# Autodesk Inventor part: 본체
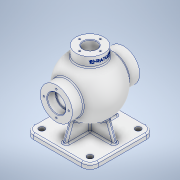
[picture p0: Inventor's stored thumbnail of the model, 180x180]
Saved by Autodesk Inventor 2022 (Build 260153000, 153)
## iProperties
Created: 2024-04
Part Number: 본체
Material: 알루미늄 6061
Document SubType Name: Modeling
Designer: user
Density: 2.7 g/cm^3
Appearance: 알루미늄 - 평지
Mass: 1526.73 g
Surface Area: 1173.98 cm^2
Volume: 565.456 cm^3
Author: user
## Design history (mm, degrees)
sketch "스케치1"
  geometry: L1 (64.8, 0)-(-10.8, 0) reference; L2 (0, -185.251)-(0, 154.667) reference; L3 (31, 65)-(31, 44.215); L4 (31, -44.215)-(31, -65); L5 (31, 65)-(0, 65); L6 (31, -65)-(0, -65); L7 (0, -65)-(0, 65); L8 (0, -136.691)-(0, 106.107); A1 r 54 centre (0, 0) between (31, -44.215) and (31, 44.215); 1 further point
  constraints: 12 end point, 4 point on line, 2 perpendicular, 2 point on circle, 2 vertical, 1 centre point, 1 coincident, 1 collinear, 1 symmetric about line
  dimensions: "d0" = 108 diameter of A1; "d2" = 31 distance between parallel lines of L4 L2; "d4" = 130 distance of L4.end L3.start
revolve "회전1" sketch "스케치1" stored, may be unused: angle "d5" = 360 deg
sketch "스케치2"
  geometry: C1 r 27 at (0, 0); 1 further point
  constraints: 1 centre point, 1 coincident
  dimensions: "d6" = 54 diameter of C1
extrude "돌출1" join sketch "스케치2" distance "d7" = 65; taper "d8" = 0 deg
node "작업 평면1"
sketch "스케치3"
  geometry: L1 (62.5, 62.5)-(-62.5, 62.5); L2 (-62.5, 62.5)-(-62.5, -62.5); L3 (-62.5, -62.5)-(62.5, -62.5); L4 (62.5, -62.5)-(62.5, 62.5); L5 (62.5, 62.5)-(-62.5, -62.5); L6 (-62.5, 62.5)-(62.5, -62.5); 1 further point
  constraints: 12 end point, 2 midpoint, 2 parallel, 1 horizontal, 1 perpendicular
  dimensions: "d10" = 125 distance of L3.end L1.start; "d11" = 125 distance of L2.end L3.end
extrude "돌출2" join sketch "스케치3" distance "d12" = 10; taper "d13" = 0 deg
sketch "스케치4"
  geometry: L1 (0, 23.202)-(0, -23.202); L2 (0, -23.202)-(-75, -50.5); L3 (-75, -62.5)-(-75, 62.5) reference; L4 (0, 23.202)-(-75, 50.5); L5 (-75, 50.5)-(-75, -50.5); L6 (-102, 0)-(17, 0) reference; L7 (0, -87.5)-(0, 87.5) reference; L8 (-85, -62.5)-(-75, -62.5) reference; 2 further points
  constraints: 8 end point, 2 symmetric about line, 1 collinear, 1 parallel, 1 point on line, 1 vertical
  dimensions: "d14" = 20 deg angle of L8 L2; "d15" = 12 distance of L3.start L2.end
extrude "돌출3" join sketch "스케치4" stored distance "d16" = 8; taper "d17" = 0 deg
sketch "스케치5"
  geometry: L1 (-23.202, 0)-(23.202, 0); L2 (23.202, 0)-(50.5, -75); L3 (62.5, -75)-(-62.5, -75) reference; L4 (-23.202, 0)-(-50.5, -75); L5 (-50.5, -75)-(50.5, -75); L6 (0, -102)-(0, 17) reference; L7 (62.5, -85)-(62.5, -75) reference; L8 (-62.5, -85)-(-62.5, -75) reference; L9 (-87.5, 0)-(87.5, 0) reference; 1 further point
  constraints: 8 end point, 2 point on line, 2 symmetric about line, 1 collinear, 1 horizontal, 1 parallel
  dimensions: "d20" = 20 deg angle of L8 L4; "d21" = 12 distance of L3.end L4.end
extrude "돌출4" join sketch "스케치5" stored distance "d22" = 8; taper "d23" = 0 deg
sketch "스케치6"
  geometry: L1 (-31, -65)-(31, -65) reference; L2 (0, -65)-(17.5, -65); L3 (17.5, -65)-(17.5, -49); L4 (17.5, -49)-(0, -49); L5 (0, -49)-(0, -65); L6 (0, -49)-(15, -49); L7 (15, -49)-(15, -41.364); L8 (15, -41.364)-(0, -41.364); L9 (0, -41.364)-(0, -49); L10 (0, -91)-(0, 91) reference; L11 (75.6, 0)-(-75.6, 0) reference; L12 (-31, 65)-(31, 65) reference; L13 (0, 65)-(17.5, 65); L14 (17.5, 65)-(17.5, 49); L15 (17.5, 49)-(0, 49); L16 (0, 49)-(0, 65); L17 (0, 49)-(15, 49); L18 (15, 49)-(15, 41.364); L19 (15, 41.364)-(0, 41.364); L20 (0, 41.364)-(0, 49); L21 (0, 41.364)-(0, -41.364); A1 r 54 centre (0, 0) between (31, -44.215) and (-31, -44.215) reference; A2 r 44 centre (0, 0) between (15, -41.364) and (15, 41.364); 6 further points
  constraints: 34 end point, 8 parallel, 4 horizontal, 4 perpendicular, 4 point on line, 2 midpoint, 2 point on circle, 1 centre point, 1 collinear
  dimensions: "d25" = 16 distance of L2.end L3.end; "d26" = 35 diameter of L3 L10; "d27" = 30 diameter of L7 L10; "d28" = 35 diameter of L14 L10; "d29" = 30 diameter of L18 L10; "d30" = 16 distance of L13.end L14.end; "d31" = 44 radius of A2
revolve "회전2" sketch "스케치6" stored, may be unused: angle "d32" = 360 deg
sketch "스케치7"
  geometry: C1 r 13 at (0, 0); 1 further point
  constraints: 1 centre point, 1 coincident
  dimensions: "d33" = 26 diameter of C1
extrude "돌출5" cut sketch "스케치7" stored distance "d34" = 8; taper "d35" = 0 deg
fillet "모깎기1" dims "d36" = 16
sketch "스케치8"
  geometry: L1 (-62.5, 46.5)-(-62.5, -46.5) reference; L2 (-46.5, -62.5)-(46.5, -62.5) reference; L3 (62.5, -46.5)-(62.5, 46.5) reference; L4 (46.5, 62.5)-(-46.5, 62.5) reference; L5 (-4, -4)-(-50.5, -4) reference; L6 (-50.5, -4)-(-50.5, 4) reference; L7 (-50.5, 4)-(-4, 4) reference; L8 (-4, 4)-(-4, 50.5) reference; L9 (-4, 50.5)-(4, 50.5) reference; L10 (4, 50.5)-(4, 4) reference; L11 (4, 4)-(50.5, 4) reference; L12 (50.5, 4)-(50.5, -4) reference; L13 (50.5, -4)-(4, -4) reference; L14 (4, -4)-(4, -50.5) reference; L15 (4, -50.5)-(-4, -50.5) reference; L16 (-4, -50.5)-(-4, -4) reference; A1 r 16 centre (-46.5, 46.5) between (-46.5, 62.5) and (-62.5, 46.5) reference; A2 r 16 centre (-46.5, -46.5) between (-62.5, -46.5) and (-46.5, -62.5) reference; A3 r 16 centre (46.5, -46.5) between (46.5, -62.5) and (62.5, -46.5) reference; A4 r 16 centre (46.5, 46.5) between (62.5, 46.5) and (46.5, 62.5) reference; 5 further points
  constraints: 4 coincident
hole "구멍1" sketch "스케치8" at (-46.5, 46.5), (46.5, 46.5), (46.5, -46.5), (-46.5, -46.5) diameter "d37" = 11; stored, may be unused: countersink angle "d41" = 90 deg, drill point angle "d43" = 118 deg; dims "d38" = 30, "d39" = 4, "d40" = 2, "d42" = 30
node "작업 평면2"
sketch "스케치9"
  geometry: L1 (65, -27)-(65, 27) reference; 2 further points
  constraints: 1 horizontal alignment, 1 other
  dimensions: "d45" = 9 distance from line of L1 point (56, 0)
feature "엠보싱1" sketch "스케치9" dims "d46" = 0.5, "d47" = 0
chamfer "모따기1" distance "d48" = 1; stored, may be unused: second distance "d49" = 2, angle "d50" = 45 deg
fillet "모깎기2" dims "d51" = 0.6
sketch "스케치10" dims "d52" = 48
  geometry: 3 further points
  constraints: 2 vertical alignment, 1 coincident, 2 other
hole "구멍2" sketch "스케치10" at (0, 24) diameter "d53" = 3.242; stored, may be unused: countersink angle "d57" = 90 deg, drill point angle "d59" = 118 deg; dims "d54" = 12, "d55" = 4, "d56" = 2, "d58" = 15
sketch "스케치11" dims "d63" = 40
  geometry: 3 further points
  constraints: 2 vertical alignment, 1 coincident, 2 other
hole "구멍3" sketch "스케치11" at (0, 20) diameter "d64" = 3.242; stored, may be unused: countersink angle "d68" = 90 deg, drill point angle "d70" = 118 deg; dims "d65" = 9, "d66" = 4, "d67" = 2, "d69" = 11
fillet "모깎기3" dims "d74" = 3
fillet "모깎기4" dims "d75" = 3
node "솔리드1"
pattern_circular "원형 패턴1" dims angle "d61" = 360 deg
mirror "미러1"
pattern_circular "원형 패턴2" dims angle "d72" = 360 deg
node "투영된 루프1"
feature "A9D066F2-1C7D-4E18-AEED-F7BC21143FA4" dims "d37" = 11, "d38" = 30, "d39" = 4, "d40" = 2, "d41" = 90 deg, "d42" = 30, "d43" = 118 deg
other parameters: "d1" = 31, "d9" = -85, "d44" = 54
